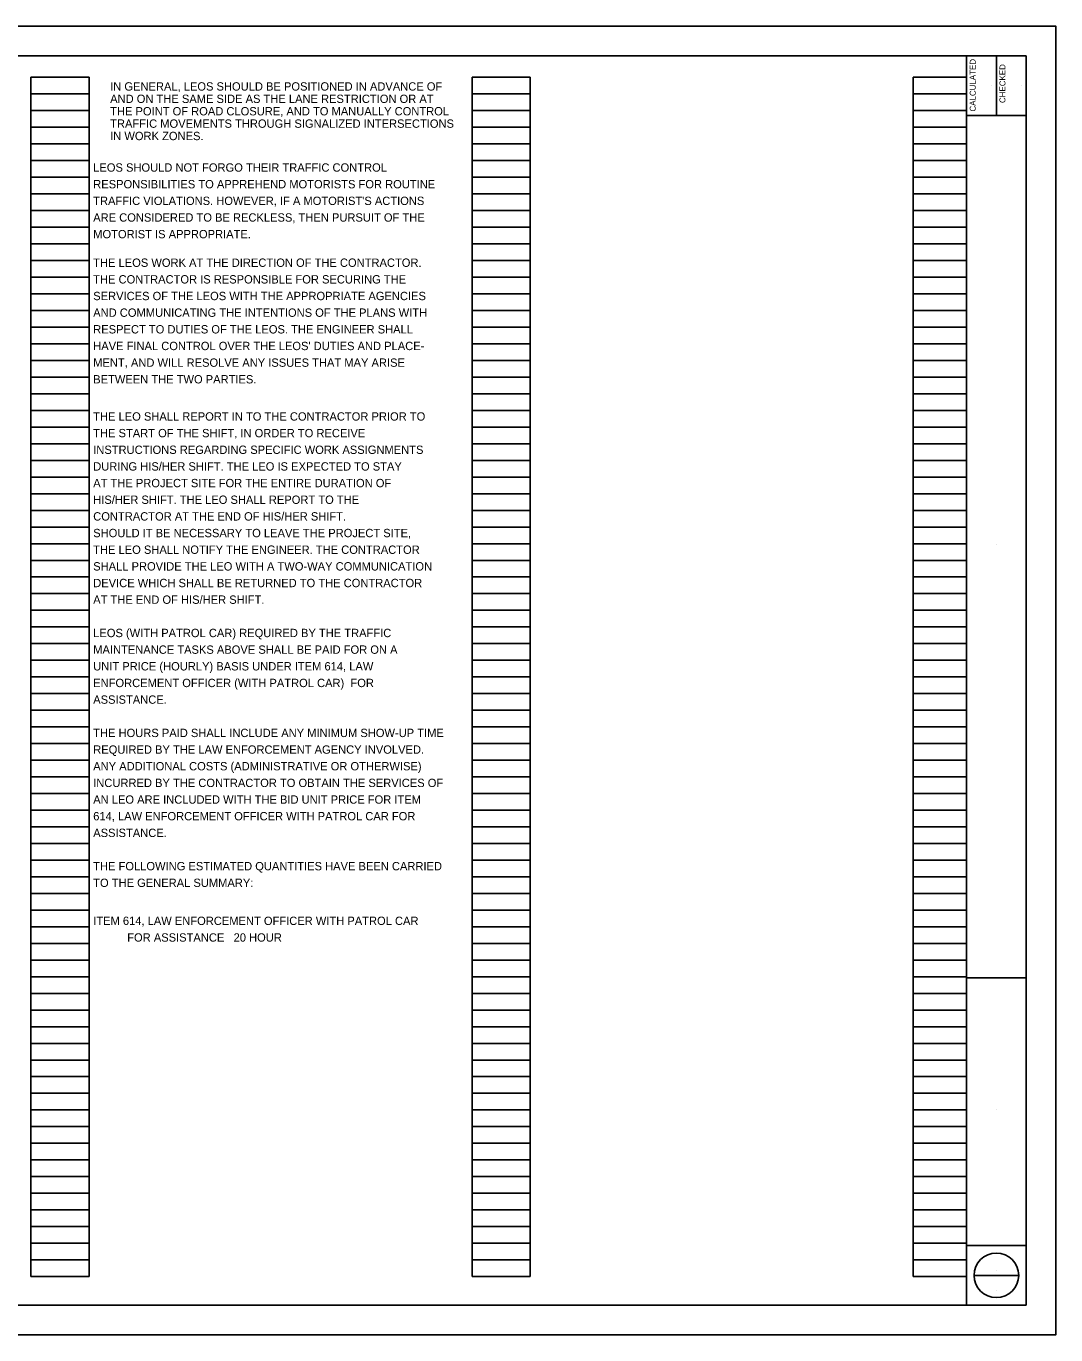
# Model space of a CAD drawing. Extents: x 0 to 34, y 0 to 22.
# Drawn here: x 16.68 to 34, y 0 to 22 of the extents above; entities that cross this region are included whole.
import ezdxf

# ---------------------------------------------------------------- set-up
doc = ezdxf.new("R2010")
doc.units = 0
for name, color, linetype in [('SH_Border', 7, 'Continuous'), ('SH_Cut_Line', 7, 'Continuous'), ('SH_Data', 7, 'Continuous'), ('SH_Text', 7, 'Continuous')]:
    doc.layers.add(name, color=color, linetype=linetype)

msp = doc.modelspace()

# ---------------------------------------------------------------- linework, layer by layer
at = {"layer": 'SH_Border'}
for p, q in [((32.5, 0.5), (32.5, 21.5)), ((33, 21.5), (33, 20.5)), ((32.5, 20.5), (33.5, 20.5)), ((32.5, 6), (33.5, 6)), ((32.5, 1.5), (33.5, 1.5))]:
    msp.add_line(p, q, dxfattribs=at)
msp.add_lwpolyline([(2, 21.5), (33.5, 21.5), (33.5, 0.5), (2, 0.5)], close=True, dxfattribs=at)
at = {"layer": 'SH_Cut_Line'}
msp.add_lwpolyline([(0, 0), (34, 0), (34, 22), (0, 22)], close=True, dxfattribs=at)
at = {"layer": 'SH_Data'}
for p, q in [((16.76, 0.98), (16.76, 21.14)), ((16.76, 21.14), (17.74, 21.14)), ((17.74, 0.98), (17.74, 21.14)), ((24.18, 0.98), (24.18, 21.14)), ((24.18, 21.14), (25.16, 21.14)), ((25.16, 0.98), (25.16, 21.14)), ((31.6, 0.98), (31.6, 21.14)), ((31.6, 21.14), (32.5, 21.14)), ((32.5, 0.98), (32.5, 21.14)), ((32.92, 21.004), (32.92, 21.004)), ((33.42, 21.004), (33.42, 21.004)), ((16.76, 20.86), (17.74, 20.86)), ((24.18, 20.86), (25.16, 20.86)), ((31.6, 20.86), (32.5, 20.86)), ((16.76, 20.58), (17.74, 20.58)), ((24.18, 20.58), (25.16, 20.58)), ((31.6, 20.58), (32.5, 20.58)), ((16.76, 20.3), (17.74, 20.3)), ((24.18, 20.3), (25.16, 20.3)), ((31.6, 20.3), (32.5, 20.3)), ((16.76, 20.02), (17.74, 20.02)), ((24.18, 20.02), (25.16, 20.02)), ((31.6, 20.02), (32.5, 20.02)), ((16.76, 19.74), (17.74, 19.74)), ((24.18, 19.74), (25.16, 19.74)), ((31.6, 19.74), (32.5, 19.74)), ((16.76, 19.46), (17.74, 19.46)), ((24.18, 19.46), (25.16, 19.46)), ((31.6, 19.46), (32.5, 19.46)), ((16.76, 19.18), (17.74, 19.18)), ((24.18, 19.18), (25.16, 19.18)), ((31.6, 19.18), (32.5, 19.18)), ((16.76, 18.9), (17.74, 18.9)), ((24.18, 18.9), (25.16, 18.9)), ((31.6, 18.9), (32.5, 18.9)), ((16.76, 18.62), (17.74, 18.62)), ((24.18, 18.62), (25.16, 18.62)), ((31.6, 18.62), (32.5, 18.62)), ((16.76, 18.34), (17.74, 18.34)), ((24.18, 18.34), (25.16, 18.34)), ((31.6, 18.34), (32.5, 18.34)), ((16.76, 18.06), (17.74, 18.06)), ((24.18, 18.06), (25.16, 18.06)), ((31.6, 18.06), (32.5, 18.06)), ((16.76, 17.78), (17.74, 17.78)), ((24.18, 17.78), (25.16, 17.78)), ((31.6, 17.78), (32.5, 17.78)), ((16.76, 17.5), (17.74, 17.5)), ((24.18, 17.5), (25.16, 17.5)), ((31.6, 17.5), (32.5, 17.5)), ((16.76, 17.22), (17.74, 17.22)), ((24.18, 17.22), (25.16, 17.22)), ((31.6, 17.22), (32.5, 17.22)), ((16.76, 16.94), (17.74, 16.94)), ((24.18, 16.94), (25.16, 16.94)), ((31.6, 16.94), (32.5, 16.94)), ((16.76, 16.66), (17.74, 16.66)), ((24.18, 16.66), (25.16, 16.66)), ((31.6, 16.66), (32.5, 16.66)), ((16.76, 16.38), (17.74, 16.38)), ((24.18, 16.38), (25.16, 16.38)), ((31.6, 16.38), (32.5, 16.38)), ((16.76, 16.1), (17.74, 16.1)), ((24.18, 16.1), (25.16, 16.1)), ((31.6, 16.1), (32.5, 16.1)), ((16.76, 15.82), (17.74, 15.82)), ((24.18, 15.82), (25.16, 15.82)), ((31.6, 15.82), (32.5, 15.82)), ((16.76, 15.54), (17.74, 15.54)), ((24.18, 15.54), (25.16, 15.54)), ((31.6, 15.54), (32.5, 15.54)), ((16.76, 15.26), (17.74, 15.26)), ((24.18, 15.26), (25.16, 15.26)), ((31.6, 15.26), (32.5, 15.26)), ((16.76, 14.98), (17.74, 14.98)), ((24.18, 14.98), (25.16, 14.98)), ((31.6, 14.98), (32.5, 14.98)), ((16.76, 14.7), (17.74, 14.7)), ((24.18, 14.7), (25.16, 14.7)), ((31.6, 14.7), (32.5, 14.7)), ((16.76, 14.42), (17.74, 14.42)), ((24.18, 14.42), (25.16, 14.42)), ((31.6, 14.42), (32.5, 14.42)), ((16.76, 14.14), (17.74, 14.14)), ((24.18, 14.14), (25.16, 14.14)), ((31.6, 14.14), (32.5, 14.14)), ((16.76, 13.86), (17.74, 13.86)), ((24.18, 13.86), (25.16, 13.86)), ((31.6, 13.86), (32.5, 13.86)), ((16.76, 13.58), (17.74, 13.58)), ((24.18, 13.58), (25.16, 13.58)), ((31.6, 13.58), (32.5, 13.58)), ((16.76, 13.3), (17.74, 13.3)), ((24.18, 13.3), (25.16, 13.3)), ((31.6, 13.3), (32.5, 13.3)), ((33, 13.292), (33, 13.292)), ((16.76, 13.02), (17.74, 13.02)), ((24.18, 13.02), (25.16, 13.02)), ((31.6, 13.02), (32.5, 13.02)), ((16.76, 12.74), (17.74, 12.74)), ((24.18, 12.74), (25.16, 12.74)), ((31.6, 12.74), (32.5, 12.74)), ((16.76, 12.46), (17.74, 12.46)), ((24.18, 12.46), (25.16, 12.46)), ((31.6, 12.46), (32.5, 12.46)), ((16.76, 12.18), (17.74, 12.18)), ((24.18, 12.18), (25.16, 12.18)), ((31.6, 12.18), (32.5, 12.18)), ((16.76, 11.9), (17.74, 11.9)), ((24.18, 11.9), (25.16, 11.9)), ((31.6, 11.9), (32.5, 11.9)), ((16.76, 11.62), (17.74, 11.62)), ((24.18, 11.62), (25.16, 11.62)), ((31.6, 11.62), (32.5, 11.62)), ((16.76, 11.34), (17.74, 11.34)), ((24.18, 11.34), (25.16, 11.34)), ((31.6, 11.34), (32.5, 11.34)), ((16.76, 11.06), (17.74, 11.06)), ((24.18, 11.06), (25.16, 11.06)), ((31.6, 11.06), (32.5, 11.06)), ((16.76, 10.78), (17.74, 10.78)), ((24.18, 10.78), (25.16, 10.78)), ((31.6, 10.78), (32.5, 10.78)), ((16.76, 10.5), (17.74, 10.5)), ((24.18, 10.5), (25.16, 10.5)), ((31.6, 10.5), (32.5, 10.5)), ((16.76, 10.22), (17.74, 10.22)), ((24.18, 10.22), (25.16, 10.22)), ((31.6, 10.22), (32.5, 10.22)), ((16.76, 9.94), (17.74, 9.94)), ((24.18, 9.94), (25.16, 9.94)), ((31.6, 9.94), (32.5, 9.94)), ((16.76, 9.66), (17.74, 9.66)), ((24.18, 9.66), (25.16, 9.66)), ((31.6, 9.66), (32.5, 9.66)), ((16.76, 9.38), (17.74, 9.38)), ((24.18, 9.38), (25.16, 9.38)), ((31.6, 9.38), (32.5, 9.38)), ((16.76, 9.1), (17.74, 9.1)), ((24.18, 9.1), (25.16, 9.1)), ((31.6, 9.1), (32.5, 9.1)), ((16.76, 8.82), (17.74, 8.82)), ((24.18, 8.82), (25.16, 8.82)), ((31.6, 8.82), (32.5, 8.82)), ((16.76, 8.54), (17.74, 8.54)), ((24.18, 8.54), (25.16, 8.54)), ((31.6, 8.54), (32.5, 8.54)), ((16.76, 8.26), (17.74, 8.26)), ((24.18, 8.26), (25.16, 8.26)), ((31.6, 8.26), (32.5, 8.26)), ((16.76, 7.98), (17.74, 7.98)), ((24.18, 7.98), (25.16, 7.98)), ((31.6, 7.98), (32.5, 7.98)), ((16.76, 7.7), (17.74, 7.7)), ((24.18, 7.7), (25.16, 7.7)), ((31.6, 7.7), (32.5, 7.7)), ((16.76, 7.42), (17.74, 7.42)), ((24.18, 7.42), (25.16, 7.42)), ((31.6, 7.42), (32.5, 7.42)), ((16.76, 7.14), (17.74, 7.14)), ((24.18, 7.14), (25.16, 7.14)), ((31.6, 7.14), (32.5, 7.14)), ((16.76, 6.86), (17.74, 6.86)), ((24.18, 6.86), (25.16, 6.86)), ((31.6, 6.86), (32.5, 6.86)), ((16.76, 6.58), (17.74, 6.58)), ((24.18, 6.58), (25.16, 6.58)), ((31.6, 6.58), (32.5, 6.58)), ((16.76, 6.3), (17.74, 6.3)), ((24.18, 6.3), (25.16, 6.3)), ((31.6, 6.3), (32.5, 6.3)), ((16.76, 6.02), (17.74, 6.02)), ((24.18, 6.02), (25.16, 6.02)), ((31.6, 6.02), (32.5, 6.02)), ((16.76, 5.74), (17.74, 5.74)), ((24.18, 5.74), (25.16, 5.74)), ((31.6, 5.74), (32.5, 5.74)), ((16.76, 5.46), (17.74, 5.46)), ((24.18, 5.46), (25.16, 5.46)), ((31.6, 5.46), (32.5, 5.46)), ((16.76, 5.18), (17.74, 5.18)), ((24.18, 5.18), (25.16, 5.18)), ((31.6, 5.18), (32.5, 5.18)), ((16.76, 4.9), (17.74, 4.9)), ((24.18, 4.9), (25.16, 4.9)), ((31.6, 4.9), (32.5, 4.9)), ((16.76, 4.62), (17.74, 4.62)), ((24.18, 4.62), (25.16, 4.62)), ((31.6, 4.62), (32.5, 4.62)), ((16.76, 4.34), (17.74, 4.34)), ((24.18, 4.34), (25.16, 4.34)), ((31.6, 4.34), (32.5, 4.34)), ((16.76, 4.06), (17.74, 4.06)), ((24.18, 4.06), (25.16, 4.06)), ((31.6, 4.06), (32.5, 4.06)), ((16.76, 3.78), (17.74, 3.78)), ((24.18, 3.78), (25.16, 3.78)), ((31.6, 3.78), (32.5, 3.78)), ((33, 3.792), (33, 3.792)), ((16.76, 3.5), (17.74, 3.5)), ((24.18, 3.5), (25.16, 3.5)), ((31.6, 3.5), (32.5, 3.5)), ((16.76, 3.22), (17.74, 3.22)), ((24.18, 3.22), (25.16, 3.22)), ((31.6, 3.22), (32.5, 3.22)), ((16.76, 2.94), (17.74, 2.94)), ((24.18, 2.94), (25.16, 2.94)), ((31.6, 2.94), (32.5, 2.94)), ((16.76, 2.66), (17.74, 2.66)), ((24.18, 2.66), (25.16, 2.66)), ((31.6, 2.66), (32.5, 2.66)), ((16.76, 2.38), (17.74, 2.38)), ((24.18, 2.38), (25.16, 2.38)), ((31.6, 2.38), (32.5, 2.38)), ((16.76, 2.1), (17.74, 2.1)), ((24.18, 2.1), (25.16, 2.1)), ((31.6, 2.1), (32.5, 2.1)), ((16.76, 1.82), (17.74, 1.82)), ((24.18, 1.82), (25.16, 1.82)), ((31.6, 1.82), (32.5, 1.82)), ((16.76, 1.54), (17.74, 1.54)), ((24.18, 1.54), (25.16, 1.54)), ((31.6, 1.54), (32.5, 1.54)), ((16.76, 1.26), (17.74, 1.26)), ((24.18, 1.26), (25.16, 1.26)), ((31.6, 1.26), (32.5, 1.26)), ((16.76, 0.98), (17.74, 0.98)), ((24.18, 0.98), (25.16, 0.98)), ((31.6, 0.98), (32.5, 0.98)), ((32.625, 1), (33.375, 1)), ((33, 1.085), (33, 1.085)), ((33, 0.745), (33, 0.745))]:
    msp.add_line(p, q, dxfattribs=at)
msp.add_circle((33, 1), 0.375, dxfattribs=at)

# ---------------------------------------------------------------- texts
for s, p in [('CALCULATED', (32.652, 20.565)), ('CHECKED', (33.152, 20.708))]:
    msp.add_text(s, height=0.1, rotation=90, dxfattribs=at).set_placement(p)
at = {"layer": 'SH_Text'}
for s, p in [('IN GENERAL, LEOS SHOULD BE POSITIONED IN ADVANCE OF ', (18.093, 20.917)), ('AND ON THE SAME SIDE AS THE LANE RESTRICTION OR AT ', (18.093, 20.709)), ('THE POINT OF ROAD CLOSURE, AND TO MANUALLY CONTROL ', (18.093, 20.5)), ('TRAFFIC MOVEMENTS THROUGH SIGNALIZED INTERSECTIONS ', (18.093, 20.292)), ('IN WORK ZONES.', (18.093, 20.084)), ('LEOS SHOULD NOT FORGO THEIR TRAFFIC CONTROL', (17.808, 19.554)), ('RESPONSIBILITIES TO APPREHEND MOTORISTS FOR ROUTINE', (17.808, 19.274)), ("TRAFFIC VIOLATIONS. HOWEVER, IF A MOTORIST'S ACTIONS", (17.808, 18.994)), ('ARE CONSIDERED TO BE RECKLESS, THEN PURSUIT OF THE', (17.808, 18.714)), ('MOTORIST IS APPROPRIATE.', (17.808, 18.434)), ('THE LEOS WORK AT THE DIRECTION OF THE CONTRACTOR.', (17.808, 17.954)), ('THE CONTRACTOR IS RESPONSIBLE FOR SECURING THE', (17.808, 17.674)), ('SERVICES OF THE LEOS WITH THE APPROPRIATE AGENCIES', (17.808, 17.394)), ('AND COMMUNICATING THE INTENTIONS OF THE PLANS WITH', (17.808, 17.114)), ('RESPECT TO DUTIES OF THE LEOS. THE ENGINEER SHALL', (17.808, 16.834)), ("HAVE FINAL CONTROL OVER THE LEOS' DUTIES AND PLACE-", (17.808, 16.554)), ('MENT, AND WILL RESOLVE ANY ISSUES THAT MAY ARISE', (17.808, 16.274)), ('BETWEEN THE TWO PARTIES.', (17.808, 15.994)), ('THE LEO SHALL REPORT IN TO THE CONTRACTOR PRIOR TO', (17.808, 15.369)), ('THE START OF THE SHIFT, IN ORDER TO RECEIVE', (17.808, 15.089)), ('INSTRUCTIONS REGARDING SPECIFIC WORK ASSIGNMENTS', (17.808, 14.809)), ('DURING HIS/HER SHIFT. THE LEO IS EXPECTED TO STAY', (17.808, 14.529)), ('AT THE PROJECT SITE FOR THE ENTIRE DURATION OF', (17.808, 14.249)), ('HIS/HER SHIFT. THE LEO SHALL REPORT TO THE', (17.808, 13.969)), ('CONTRACTOR AT THE END OF HIS/HER SHIFT. ', (17.808, 13.689)), ('SHOULD IT BE NECESSARY TO LEAVE THE PROJECT SITE, ', (17.808, 13.409)), ('THE LEO SHALL NOTIFY THE ENGINEER. THE CONTRACTOR ', (17.808, 13.129)), ('SHALL PROVIDE THE LEO WITH A TWO-WAY COMMUNICATION ', (17.808, 12.849)), ('DEVICE WHICH SHALL BE RETURNED TO THE CONTRACTOR ', (17.808, 12.569)), ('AT THE END OF HIS/HER SHIFT. ', (17.808, 12.289)), ('LEOS (WITH PATROL CAR) REQUIRED BY THE TRAFFIC ', (17.808, 11.729)), ('MAINTENANCE TASKS ABOVE SHALL BE PAID FOR ON A ', (17.808, 11.449)), ('UNIT PRICE (HOURLY) BASIS UNDER ITEM 614, LAW ', (17.808, 11.169)), ('ENFORCEMENT OFFICER (WITH PATROL CAR)  FOR ', (17.808, 10.889)), ('ASSISTANCE.', (17.808, 10.609)), ('THE HOURS PAID SHALL INCLUDE ANY MINIMUM SHOW-UP TIME', (17.808, 10.049)), ('REQUIRED BY THE LAW ENFORCEMENT AGENCY INVOLVED.', (17.808, 9.769)), ('ANY ADDITIONAL COSTS (ADMINISTRATIVE OR OTHERWISE)', (17.808, 9.489)), ('INCURRED BY THE CONTRACTOR TO OBTAIN THE SERVICES OF', (17.808, 9.209)), ('AN LEO ARE INCLUDED WITH THE BID UNIT PRICE FOR ITEM', (17.808, 8.929)), ('614, LAW ENFORCEMENT OFFICER WITH PATROL CAR FOR', (17.808, 8.649)), ('ASSISTANCE.', (17.808, 8.369)), ('THE FOLLOWING ESTIMATED QUANTITIES HAVE BEEN CARRIED', (17.808, 7.809)), ('TO THE GENERAL SUMMARY:', (17.808, 7.529)), ('ITEM 614, LAW ENFORCEMENT OFFICER WITH PATROL CAR', (17.808, 6.89)), ('           FOR ASSISTANCE   20 HOUR', (17.808, 6.61))]:
    msp.add_text(s, height=0.14, dxfattribs=at).set_placement(p)

doc.saveas('drawing.dxf')
